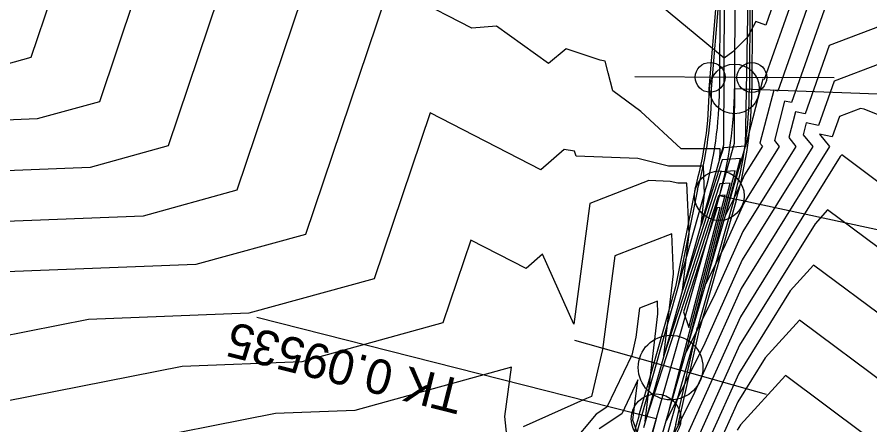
# Model space of a CAD drawing. Extents: x -549394 to -546608, y -1037055 to -1033629.
# Drawn here: x -547510.8 to -547425.1, y -1035932.6 to -1035891.5 of the extents above; entities that cross this region are included whole.
import ezdxf

# ---------------------------------------------------------------- set-up
doc = ezdxf.new("R2010")
doc.units = 0
for name, color, linetype in [('hlavni_vrst', 7, 'Continuous'), ('hrana_L', 7, 'Continuous'), ('norm_vrst', 7, 'Continuous'), ('POLYGONY_SITUACE_PO', 7, 'Continuous'), ('u_sirka_1_5m', 7, 'Continuous'), ('x_navrh_C41', 7, 'Continuous'), ('x_osa_C41', 7, 'Continuous'), ('x_popis_oblouky_C41', 7, 'Continuous'), ('x_popis_pricne_rezy_C41', 7, 'Continuous')]:
    doc.layers.add(name, color=color, linetype=linetype)

msp = doc.modelspace()

# ---------------------------------------------------------------- linework, layer by layer
at = {"layer": 'hlavni_vrst'}
for p, q in [((-547504.576, -1035881.362), (-547509.381, -1035895.618)), ((-547430.188, -1035887.283), (-547434.32, -1035898.993)), ((-547509.381, -1035895.618), (-547514.053, -1035896.905)), ((-547434.728, -1035898.905), (-547436.109, -1035904.248)), ((-547434.32, -1035898.993), (-547434.728, -1035898.905)), ((-547469.251, -1035901.186), (-547474.873, -1035917.869)), ((-547458.141, -1035906.92), (-547469.251, -1035901.186)), ((-547455.792, -1035904.885), (-547458.141, -1035906.92)), ((-547454.759, -1035905.05), (-547455.792, -1035904.885)), ((-547435.867, -1035904.547), (-547437.656, -1035907.422)), ((-547436.109, -1035904.248), (-547435.867, -1035904.547)), ((-547454.579, -1035905.547), (-547454.759, -1035905.05)), ((-547448.385, -1035905.769), (-547454.579, -1035905.547)), ((-547445.304, -1035906.535), (-547448.385, -1035905.769)), ((-547438.083, -1035905.784), (-547439.909, -1035905.91)), ((-547439.571, -1035911.489), (-547438.083, -1035905.784)), ((-547428.066, -1035905.591), (-547438.079, -1035921.688)), ((-547427.902, -1035905.412), (-547428.066, -1035905.591)), ((-547398.184, -1035927.622), (-547427.902, -1035905.412)), ((-547441.795, -1035906.546), (-547445.304, -1035906.535)), ((-547439.909, -1035905.91), (-547442.036, -1035912.472)), ((-547441.67, -1035909.338), (-547441.795, -1035906.546)), ((-547437.656, -1035907.422), (-547438.602, -1035909.53)), ((-547442.036, -1035912.472), (-547441.67, -1035909.338)), ((-547438.602, -1035909.53), (-547439.571, -1035911.489)), ((-547474.873, -1035917.869), (-547487.465, -1035921.338)), ((-547503.569, -1035921.962), (-547518.4, -1035924.884)), ((-547487.465, -1035921.338), (-547503.569, -1035921.962)), ((-547438.079, -1035921.688), (-547443.553, -1035933.884))]:
    msp.add_line(p, q, dxfattribs=at)
at = {"layer": 'hrana_L'}
for p, q in [((-547439.64, -1035876.54), (-547439.76, -1035904.44)), ((-547437.57, -1035904.54), (-547437.07, -1035876.65)), ((-547439.76, -1035904.44), (-547447.82, -1035932.88)), ((-547446.03, -1035933.92), (-547437.57, -1035904.54))]:
    msp.add_line(p, q, dxfattribs=at)
at = {"layer": 'norm_vrst'}
for p, q in [((-547496.046, -1035880.979), (-547502.479, -1035900.068)), ((-547487.516, -1035880.596), (-547495.578, -1035904.519)), ((-547478.986, -1035880.214), (-547488.676, -1035908.969)), ((-547431.218, -1035880.151), (-547435.526, -1035892.358)), ((-547430.703, -1035883.717), (-547435.687, -1035897.841)), ((-547473.341, -1035888.395), (-547481.775, -1035913.419)), ((-547465.079, -1035892.658), (-547473.341, -1035888.395)), ((-547439.722, -1035895.7), (-547448.175, -1035888.636)), ((-547429.673, -1035890.85), (-547432.953, -1035900.145)), ((-547436.52, -1035891.987), (-547437.374, -1035893.583)), ((-547435.526, -1035892.358), (-547436.52, -1035891.987)), ((-547422.091, -1035891.731), (-547429.158, -1035894.416)), ((-547462.601, -1035892.473), (-547465.079, -1035892.658)), ((-547457.376, -1035896.236), (-547462.601, -1035892.473)), ((-547437.374, -1035893.583), (-547438.852, -1035895.056)), ((-547429.158, -1035894.416), (-547431.586, -1035901.297)), ((-547455.568, -1035894.753), (-547457.376, -1035896.236)), ((-547452.184, -1035895.881), (-547455.568, -1035894.753)), ((-547438.852, -1035895.056), (-547439.722, -1035895.7)), ((-547451.66, -1035895.985), (-547452.184, -1035895.881)), ((-547451.374, -1035897.164), (-547451.66, -1035895.985)), ((-547424.056, -1035896.24), (-547428.643, -1035897.982)), ((-547450.891, -1035898.974), (-547451.374, -1035897.164)), ((-547435.818, -1035897.813), (-547437.556, -1035904.537)), ((-547435.687, -1035897.841), (-547435.818, -1035897.813)), ((-547428.643, -1035897.982), (-547430.219, -1035902.449)), ((-547448.073, -1035901.059), (-547450.891, -1035898.974)), ((-547502.479, -1035900.068), (-547508.735, -1035901.792)), ((-547433.638, -1035899.997), (-547434.662, -1035903.959)), ((-547432.953, -1035900.145), (-547433.638, -1035899.997)), ((-547444.02, -1035904.807), (-547448.073, -1035901.059)), ((-547432.548, -1035901.088), (-547433.215, -1035903.67)), ((-547431.586, -1035901.297), (-547432.548, -1035901.088)), ((-547428.128, -1035901.549), (-547428.852, -1035903.601)), ((-547426.02, -1035900.748), (-547428.128, -1035901.549)), ((-547425.635, -1035900.806), (-547426.02, -1035900.748)), ((-547422.103, -1035902.253), (-547425.635, -1035900.806)), ((-547508.735, -1035901.792), (-547541.147, -1035903.047)), ((-547431.458, -1035902.18), (-547431.769, -1035903.381)), ((-547430.219, -1035902.449), (-547431.458, -1035902.18)), ((-547434.662, -1035903.959), (-547434.181, -1035904.554)), ((-547433.215, -1035903.67), (-547432.495, -1035904.561)), ((-547431.769, -1035903.381), (-547430.809, -1035904.567)), ((-547428.852, -1035903.601), (-547430.136, -1035903.322)), ((-547430.136, -1035903.322), (-547429.123, -1035904.574)), ((-547495.578, -1035904.519), (-547503.418, -1035906.678)), ((-547440.127, -1035904.82), (-547444.02, -1035904.807)), ((-547439.787, -1035904.705), (-547440.17, -1035905.888)), ((-547440.104, -1035905.323), (-547440.127, -1035904.82)), ((-547437.575, -1035904.552), (-547439.787, -1035904.705)), ((-547429.123, -1035904.574), (-547437.994, -1035918.835)), ((-547430.809, -1035904.567), (-547437.91, -1035915.981)), ((-547432.495, -1035904.561), (-547437.825, -1035913.128)), ((-547434.181, -1035904.554), (-547437.74, -1035910.275)), ((-547437.59, -1035904.609), (-547437.575, -1035904.552)), ((-547437.58, -1035904.589), (-547437.59, -1035904.609)), ((-547437.571, -1035904.569), (-547437.58, -1035904.589)), ((-547437.553, -1035904.54), (-547437.571, -1035904.569)), ((-547437.556, -1035904.537), (-547437.553, -1035904.54)), ((-547440.17, -1035905.888), (-547440.104, -1035905.323)), ((-547503.418, -1035906.678), (-547531.753, -1035907.776)), ((-547440.032, -1035907.114), (-547443.902, -1035919.055)), ((-547441.552, -1035918.37), (-547438.591, -1035907.015)), ((-547438.591, -1035907.015), (-547440.032, -1035907.114)), ((-547447.286, -1035907.998), (-547453.221, -1035910.292)), ((-547445.135, -1035908.076), (-547447.286, -1035907.998)), ((-547440.154, -1035908.319), (-547445.768, -1035925.638)), ((-547444.353, -1035908.27), (-547445.135, -1035908.076)), ((-547443.463, -1035908.273), (-547444.353, -1035908.27)), ((-547443.534, -1035925.25), (-547439.099, -1035908.246)), ((-547443.235, -1035913.353), (-547443.463, -1035908.273)), ((-547439.099, -1035908.246), (-547440.154, -1035908.319)), ((-547488.676, -1035908.969), (-547498.1, -1035911.565)), ((-547440.277, -1035909.524), (-547447.633, -1035932.222)), ((-547445.515, -1035932.131), (-547439.606, -1035909.478)), ((-547439.606, -1035909.478), (-547440.277, -1035909.524)), ((-547453.221, -1035910.292), (-547454.811, -1035922.439)), ((-547440.399, -1035910.729), (-547443.797, -1035921.213)), ((-547443.26, -1035922.77), (-547440.114, -1035910.709)), ((-547440.114, -1035910.709), (-547440.399, -1035910.729)), ((-547437.74, -1035910.275), (-547439.624, -1035914.472)), ((-547429.315, -1035910.956), (-547430.569, -1035912.332)), ((-547405.03, -1035929.106), (-547429.315, -1035910.956)), ((-547498.1, -1035911.565), (-547522.358, -1035912.504)), ((-547430.569, -1035912.332), (-547438.164, -1035924.541)), ((-547481.775, -1035913.419), (-547492.782, -1035916.452)), ((-547444.981, -1035913.342), (-547450.71, -1035915.557)), ((-547444.8, -1035917.368), (-547444.981, -1035913.342)), ((-547443.902, -1035919.055), (-547443.235, -1035913.353)), ((-547437.825, -1035913.128), (-547440.646, -1035919.413)), ((-547465.16, -1035913.978), (-547467.972, -1035922.32)), ((-547459.605, -1035916.845), (-547465.16, -1035913.978)), ((-547439.624, -1035914.472), (-547441.552, -1035918.37)), ((-547457.95, -1035915.411), (-547459.605, -1035916.845)), ((-547454.811, -1035922.439), (-547457.95, -1035915.411)), ((-547450.71, -1035915.557), (-547451.944, -1035924.979)), ((-547437.91, -1035915.981), (-547441.668, -1035924.354)), ((-547492.782, -1035916.452), (-547512.963, -1035917.233)), ((-547430.728, -1035916.501), (-547433.073, -1035919.074)), ((-547411.876, -1035930.59), (-547430.728, -1035916.501)), ((-547445.768, -1035925.638), (-547444.8, -1035917.368)), ((-547440.646, -1035919.413), (-547443.534, -1035925.25)), ((-547437.994, -1035918.835), (-547442.69, -1035929.295)), ((-547433.073, -1035919.074), (-547438.249, -1035927.394)), ((-547446.422, -1035920.134), (-547448.2, -1035920.821)), ((-547446.366, -1035921.383), (-547446.422, -1035920.134)), ((-547448.2, -1035920.821), (-547448.583, -1035923.745)), ((-547443.797, -1035921.213), (-547443.26, -1035922.77)), ((-547447.633, -1035932.222), (-547446.366, -1035921.383)), ((-547432.14, -1035922.045), (-547435.576, -1035925.815)), ((-547418.721, -1035932.074), (-547432.14, -1035922.045)), ((-547467.972, -1035922.32), (-547482.147, -1035926.225)), ((-547448.583, -1035923.745), (-547449.001, -1035925.544)), ((-547441.668, -1035924.354), (-547445.515, -1035932.131)), ((-547438.164, -1035924.541), (-547442.316, -1035933.791)), ((-547451.944, -1035924.979), (-547453.042, -1035929.702)), ((-547449.001, -1035925.544), (-547451.487, -1035930.793)), ((-547482.147, -1035926.225), (-547494.174, -1035926.69)), ((-547435.576, -1035925.815), (-547438.333, -1035930.247)), ((-547494.174, -1035926.69), (-547511.99, -1035930.201)), ((-547461.07, -1035926.77), (-547476.829, -1035931.111)), ((-547461.747, -1035931.709), (-547461.07, -1035926.77)), ((-547461.07, -1035926.77), (-547461.07, -1035926.77)), ((-547461.07, -1035926.77), (-547461.07, -1035926.77)), ((-547461.07, -1035926.77), (-547461.07, -1035926.77)), ((-547461.07, -1035926.77), (-547461.07, -1035926.77)), ((-547461.07, -1035926.77), (-547461.07, -1035926.77)), ((-547448.368, -1035928.038), (-547449.989, -1035931.46)), ((-547448.87, -1035932.103), (-547448.368, -1035928.038)), ((-547438.249, -1035927.394), (-547441.078, -1035933.698)), ((-547433.553, -1035927.59), (-547438.08, -1035932.556)), ((-547425.567, -1035933.559), (-547433.553, -1035927.59)), ((-547453.042, -1035929.702), (-547453.527, -1035929.909)), ((-547442.69, -1035929.295), (-547444.971, -1035933.907)), ((-547453.527, -1035929.909), (-547459.895, -1035932.75)), ((-547438.333, -1035930.247), (-547439.841, -1035933.606)), ((-547484.78, -1035931.419), (-547505.58, -1035935.518)), ((-547476.829, -1035931.111), (-547484.78, -1035931.419)), ((-547452.558, -1035931.506), (-547457.287, -1035937.096)), ((-547451.487, -1035930.793), (-547452.558, -1035931.506)), ((-547449.989, -1035931.46), (-547452.265, -1035932.972)), ((-547461.417, -1035934.735), (-547461.747, -1035931.709)), ((-547448.172, -1035934.039), (-547448.87, -1035932.103)), ((-547438.08, -1035932.556), (-547438.418, -1035933.101))]:
    msp.add_line(p, q, dxfattribs=at)
at = {"layer": 'POLYGONY_SITUACE_PO'}
for centre in [(-547438.677, -1035898.778), (-547440.193, -1035909.517), (-547446.552, -1035931.95)]:
    msp.add_circle(centre, 2.5, dxfattribs=at)
at = {"layer": 'u_sirka_1_5m'}
for centre, radius in [((-547441.121, -1035897.611), 1.5), ((-547436.922, -1035897.629), 1.5), ((-547445.092, -1035926.801), 3.25)]:
    msp.add_circle(centre, radius, dxfattribs=at)
at = {"layer": 'x_navrh_C41'}
for p, q in [((-547440.117, -1035884.763), (-547440.177, -1035898.772)), ((-547437.117, -1035884.776), (-547437.177, -1035898.784)), ((-547441.217, -1035898.757), (-547440.384, -1035888.761)), ((-547440.967, -1035898.768), (-547440.134, -1035888.772)), ((-547441.636, -1035909.108), (-547447.995, -1035931.541)), ((-547442.639, -1035908.834), (-547444.607, -1035918.67)), ((-547442.396, -1035908.893), (-547444.363, -1035918.729)), ((-547438.75, -1035909.926), (-547445.109, -1035932.359)), ((-547444.561, -1035932.514), (-547442.382, -1035922.738)), ((-547444.317, -1035932.569), (-547442.139, -1035922.799)), ((-547447.093, -1035927.443), (-547448.236, -1035931.473))]:
    msp.add_line(p, q, dxfattribs=at)
for points in [[(-547436.867, -1035884.777), (-547436.927, -1035898.786)], [(-547438.509, -1035909.995), (-547442.139, -1035922.799)], [(-547444.607, -1035918.67), (-547447.093, -1035927.443)]]:
    msp.add_lwpolyline(points, dxfattribs=at)
for centre, radius, start, end in [((-547478.676, -1035898.608), 37.46, 344.15751, 359.77104), ((-547478.676, -1035898.608), 37.71, 344.17256, 359.75599), ((-547478.676, -1035898.608), 38.5, 344.17256, 359.75599), ((-547478.676, -1035898.608), 41.5, 344.17256, 359.75599), ((-547478.676, -1035898.608), 41.75, 344.17256, 359.75599), ((-547384.016, -1035949.678), 66.5, 164.17256, 207.80768), ((-547384.016, -1035949.678), 66.75, 164.17256, 168.98151), ((-547384.016, -1035949.678), 63.5, 164.17256, 207.80768), ((-547384.016, -1035949.678), 62.93, 164.17256, 207.80768)]:
    msp.add_arc(centre, radius, start, end, dxfattribs=at)
at = {"layer": 'x_osa_C41'}
msp.add_lwpolyline([(-547441.135, -1035837.7), (-547438.579, -1035875.877), (-547438.7, -1035904.251), (-547453.649, -1035956.985)], dxfattribs=at)
for centre, radius, start, end in [((-547478.676, -1035898.608), 40, 344.17256, 359.75599), ((-547384.016, -1035949.678), 65, 164.17256, 207.80768)]:
    msp.add_arc(centre, radius, start, end, dxfattribs=at)
at = {"layer": 'x_popis_oblouky_C41'}
for points in [[(-547397.331, -1035900.299), (-547438.677, -1035898.778)], [(-547399.751, -1035918.247), (-547440.193, -1035909.517)], [(-547446.552, -1035931.95), (-547486.655, -1035921.778)]]:
    msp.add_lwpolyline(points, dxfattribs=at)
at = {"layer": 'x_popis_pricne_rezy_C41'}
for points in [[(-547428.672, -1035897.664), (-547438.672, -1035897.622), (-547448.672, -1035897.579)], [(-547435.472, -1035929.528), (-547445.092, -1035926.801), (-547454.713, -1035924.073)]]:
    msp.add_lwpolyline(points, dxfattribs=at)

# ---------------------------------------------------------------- texts
at = {"layer": 'x_popis_oblouky_C41'}
msp.add_text('TK 0.09535', height=3.5, rotation=165.76692, dxfattribs=at).set_placement((-547465.654, -1035928.131))

doc.saveas('drawing.dxf')
